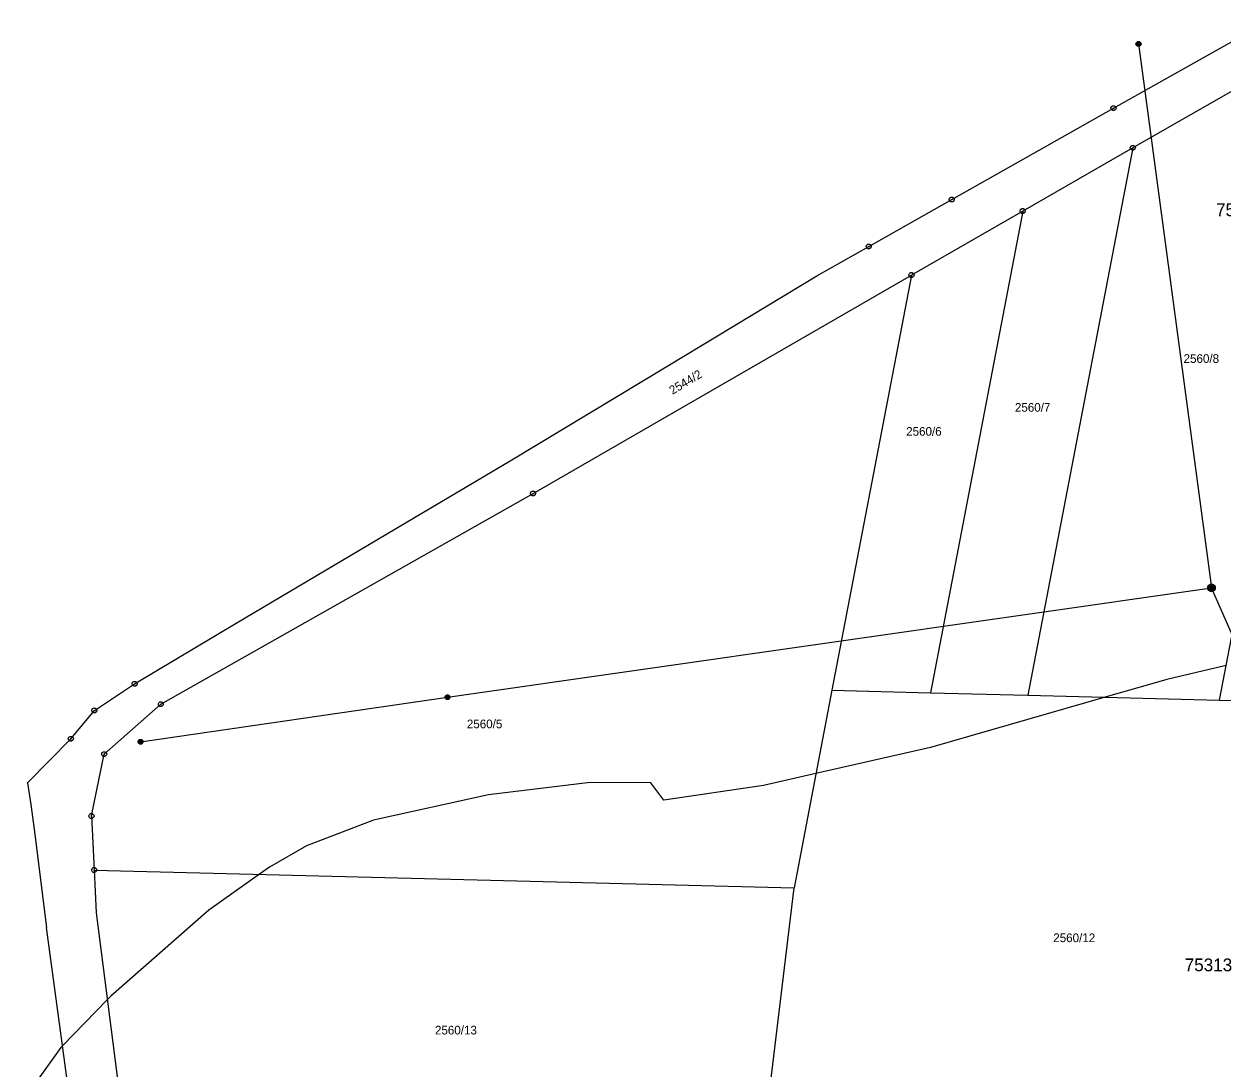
# Model space of a CAD drawing. Extents: x -760611 to -758411, y -1176479 to -1174807.
# Drawn here: x -759710.8 to -759476.2, y -1175348.2 to -1175143.7 of the extents above; entities that cross this region are included whole.
import ezdxf

# ---------------------------------------------------------------- set-up
doc = ezdxf.new("R2010")
doc.units = 0
for name, color, linetype in [('1', 7, 'Continuous'), ('11', 7, 'Continuous'), ('2', 7, 'Continuous'), ('6', 7, 'Continuous'), ('8', 7, 'Continuous')]:
    doc.layers.add(name, color=color, linetype=linetype)

msp = doc.modelspace()

# ---------------------------------------------------------------- linework, layer by layer
at = {"layer": '1'}
for p, q in [((-759497.47, -1175160.23), (-759471.7, -1175145.7)), ((-759451.36, -1175143.73), (-759493.7, -1175167.99)), ((-759476.73, -1175276.15), (-759451.36, -1175143.73)), ((-759529.17, -1175178.14), (-759497.47, -1175160.23)), ((-759493.7, -1175167.99), (-759515.25, -1175180.38)), ((-759493.7, -1175167.99), (-759514.23, -1175275.19)), ((-759545.4, -1175187.31), (-759529.17, -1175178.14)), ((-759515.25, -1175180.38), (-759537.04, -1175192.91)), ((-759515.25, -1175180.38), (-759533.32, -1175274.71)), ((-759555.57, -1175193.05), (-759545.4, -1175187.31)), ((-759611.14, -1175235.69), (-759537.04, -1175192.91)), ((-759584.77, -1175210.68), (-759555.57, -1175193.05)), ((-759537.04, -1175192.91), (-759552.61, -1175274.21)), ((-759615.59, -1175229.29), (-759584.77, -1175210.68)), ((-759669.25, -1175261.1), (-759615.59, -1175229.29)), ((-759684.03, -1175276.97), (-759611.14, -1175235.69)), ((-759689.15, -1175272.97), (-759669.25, -1175261.1)), ((-759697.03, -1175278.2), (-759689.15, -1175272.97)), ((-759552.61, -1175274.21), (-759560.03, -1175312.95)), ((-759552.61, -1175274.21), (-759533.32, -1175274.71)), ((-759533.32, -1175274.71), (-759514.23, -1175275.19)), ((-759695.11, -1175286.75), (-759684.03, -1175276.97)), ((-759514.23, -1175275.19), (-759476.73, -1175276.15)), ((-759476.73, -1175276.15), (-759458.35, -1175276.62)), ((-759701.63, -1175283.75), (-759697.03, -1175278.2)), ((-759701.63, -1175283.75), (-759710.1, -1175292.36)), ((-759697.6, -1175298.86), (-759695.11, -1175286.75)), ((-759710.1, -1175292.36), (-759709.49, -1175296.58)), ((-759709.49, -1175296.58), (-759708.79, -1175301.41)), ((-759697.6, -1175298.86), (-759697.08, -1175309.45)), ((-759708.79, -1175301.41), (-759706.43, -1175320.68)), ((-759697.08, -1175309.45), (-759696.67, -1175317.85)), ((-759697.08, -1175309.45), (-759560.03, -1175312.95)), ((-759565.54, -1175358.51), (-759560.03, -1175312.95)), ((-759696.67, -1175317.85), (-759689.49, -1175374.27)), ((-759691.89, -1175426.78), (-759706.43, -1175320.68))]:
    msp.add_line(p, q, dxfattribs=at)
at = {"layer": '11'}
msp.add_lwpolyline([(-759475.44, -1175269.41), (-759487.07, -1175272.11), (-759499.12, -1175275.58), (-759533.34, -1175285.42), (-759555.74, -1175290.53), (-759566.01, -1175292.87), (-759585.53, -1175295.74), (-759588.06, -1175292.34), (-759599.93, -1175292.28), (-759619.87, -1175294.72), (-759642.36, -1175299.69), (-759655.52, -1175304.7), (-759662.75, -1175308.89), (-759664.71, -1175310.28), (-759674.65, -1175317.3), (-759693.79, -1175334.13), (-759694.5, -1175334.86), (-759703.25, -1175343.89), (-759703.58, -1175344.23), (-759710.82, -1175354.35)], dxfattribs=at)
at = {"layer": '6'}
for p, q in [((-759492.59, -1175147.64), (-759478.28, -1175254.17)), ((-759627.89, -1175275.6), (-759478.28, -1175254.17)), ((-759403.75, -1175424.27), (-759478.28, -1175254.17)), ((-759687.99, -1175284.33), (-759627.89, -1175275.6))]:
    msp.add_line(p, q, dxfattribs=at)
for points in [[(-759492.74, -1175147.16), (-759492.43, -1175147.16), (-759492.18, -1175147.34), (-759492.08, -1175147.63), (-759492.18, -1175147.92), (-759492.43, -1175148.1), (-759492.74, -1175148.1), (-759492.99, -1175147.92), (-759493.09, -1175147.63), (-759492.99, -1175147.34), (-759492.74, -1175147.16), (-759492.71, -1175147.2), (-759492.47, -1175147.2), (-759492.31, -1175147.28), (-759492.87, -1175147.28), (-759492.95, -1175147.36), (-759492.23, -1175147.36), (-759492.23, -1175147.44), (-759492.95, -1175147.44), (-759492.99, -1175147.52), (-759492.19, -1175147.52), (-759492.15, -1175147.6), (-759493.03, -1175147.6), (-759493.03, -1175147.68), (-759492.15, -1175147.68), (-759492.18, -1175147.76), (-759492.99, -1175147.76), (-759492.98, -1175147.84), (-759492.17, -1175147.84), (-759492.22, -1175147.92), (-759492.94, -1175147.92), (-759492.86, -1175148), (-759492.3, -1175148), (-759492.41, -1175148.08), (-759492.75, -1175148.08)], [(-759478.78, -1175253.67), (-759477.78, -1175253.67), (-759477.78, -1175254.67), (-759478.78, -1175254.67), (-759478.78, -1175253.67), (-759478.72, -1175253.73), (-759477.84, -1175253.73), (-759477.84, -1175253.81), (-759478.72, -1175253.81), (-759478.72, -1175253.89), (-759477.84, -1175253.89), (-759477.84, -1175253.97), (-759478.72, -1175253.97), (-759478.72, -1175254.05), (-759477.84, -1175254.05), (-759477.84, -1175254.13), (-759478.72, -1175254.13), (-759478.72, -1175254.21), (-759477.84, -1175254.21), (-759477.84, -1175254.29), (-759478.72, -1175254.29), (-759478.72, -1175254.37), (-759477.84, -1175254.37), (-759477.84, -1175254.45), (-759478.72, -1175254.45), (-759478.72, -1175254.53), (-759477.84, -1175254.53), (-759477.84, -1175254.61), (-759478.72, -1175254.61)], [(-759628.04, -1175275.12), (-759627.73, -1175275.12), (-759627.48, -1175275.3), (-759627.38, -1175275.59), (-759627.48, -1175275.88), (-759627.73, -1175276.06), (-759628.04, -1175276.06), (-759628.29, -1175275.88), (-759628.39, -1175275.59), (-759628.29, -1175275.3), (-759628.04, -1175275.12), (-759628.01, -1175275.16), (-759627.77, -1175275.16), (-759627.61, -1175275.24), (-759628.17, -1175275.24), (-759628.25, -1175275.32), (-759627.53, -1175275.32), (-759627.53, -1175275.4), (-759628.25, -1175275.4), (-759628.29, -1175275.48), (-759627.49, -1175275.48), (-759627.45, -1175275.56), (-759628.33, -1175275.56), (-759628.33, -1175275.64), (-759627.45, -1175275.64), (-759627.48, -1175275.72), (-759628.29, -1175275.72), (-759628.28, -1175275.8), (-759627.47, -1175275.8), (-759627.52, -1175275.88), (-759628.24, -1175275.88), (-759628.16, -1175275.96), (-759627.6, -1175275.96), (-759627.71, -1175276.04), (-759628.05, -1175276.04)], [(-759688.14, -1175283.85), (-759687.83, -1175283.85), (-759687.58, -1175284.03), (-759687.48, -1175284.32), (-759687.58, -1175284.61), (-759687.83, -1175284.79), (-759688.14, -1175284.79), (-759688.39, -1175284.61), (-759688.49, -1175284.32), (-759688.39, -1175284.03), (-759688.14, -1175283.85), (-759688.11, -1175283.89), (-759687.87, -1175283.89), (-759687.71, -1175283.97), (-759688.27, -1175283.97), (-759688.35, -1175284.05), (-759687.63, -1175284.05), (-759687.63, -1175284.13), (-759688.35, -1175284.13), (-759688.39, -1175284.21), (-759687.59, -1175284.21), (-759687.55, -1175284.29), (-759688.43, -1175284.29), (-759688.43, -1175284.37), (-759687.55, -1175284.37), (-759687.58, -1175284.45), (-759688.39, -1175284.45), (-759688.38, -1175284.53), (-759687.57, -1175284.53), (-759687.62, -1175284.61), (-759688.34, -1175284.61), (-759688.26, -1175284.69), (-759687.7, -1175284.69), (-759687.81, -1175284.77), (-759688.15, -1175284.77)]]:
    msp.add_lwpolyline(points, dxfattribs=at)
at = {"layer": '8'}
for p, q in [((-759497.59, -1175160.23), (-759497.35, -1175160.23)), ((-759493.82, -1175167.99), (-759493.58, -1175167.99)), ((-759529.29, -1175178.14), (-759529.05, -1175178.14)), ((-759515.37, -1175180.38), (-759515.13, -1175180.38)), ((-759545.52, -1175187.31), (-759545.28, -1175187.31)), ((-759537.16, -1175192.91), (-759536.92, -1175192.91)), ((-759611.26, -1175235.69), (-759611.02, -1175235.69)), ((-759478.33, -1175254.17), (-759478.23, -1175254.17)), ((-759689.27, -1175272.97), (-759689.03, -1175272.97)), ((-759684.15, -1175276.97), (-759683.91, -1175276.97)), ((-759697.15, -1175278.2), (-759696.91, -1175278.2)), ((-759701.75, -1175283.75), (-759701.51, -1175283.75)), ((-759695.23, -1175286.75), (-759694.99, -1175286.75)), ((-759697.72, -1175298.86), (-759697.48, -1175298.86)), ((-759697.2, -1175309.45), (-759696.96, -1175309.45))]:
    msp.add_line(p, q, dxfattribs=at)
for points in [[(-759497.32, -1175159.75), (-759497.07, -1175159.93), (-759496.97, -1175160.22), (-759497.07, -1175160.51), (-759497.32, -1175160.69), (-759497.63, -1175160.69), (-759497.88, -1175160.51), (-759497.98, -1175160.22), (-759497.88, -1175159.93), (-759497.63, -1175159.75)], [(-759493.55, -1175167.51), (-759493.3, -1175167.69), (-759493.2, -1175167.98), (-759493.3, -1175168.27), (-759493.55, -1175168.45), (-759493.86, -1175168.45), (-759494.11, -1175168.27), (-759494.21, -1175167.98), (-759494.11, -1175167.69), (-759493.86, -1175167.51)], [(-759529.02, -1175177.66), (-759528.77, -1175177.84), (-759528.67, -1175178.13), (-759528.77, -1175178.42), (-759529.02, -1175178.6), (-759529.33, -1175178.6), (-759529.58, -1175178.42), (-759529.68, -1175178.13), (-759529.58, -1175177.84), (-759529.33, -1175177.66)], [(-759515.1, -1175179.9), (-759514.85, -1175180.08), (-759514.75, -1175180.37), (-759514.85, -1175180.66), (-759515.1, -1175180.84), (-759515.41, -1175180.84), (-759515.66, -1175180.66), (-759515.76, -1175180.37), (-759515.66, -1175180.08), (-759515.41, -1175179.9)], [(-759545.25, -1175186.83), (-759545, -1175187.01), (-759544.9, -1175187.3), (-759545, -1175187.59), (-759545.25, -1175187.77), (-759545.56, -1175187.77), (-759545.81, -1175187.59), (-759545.91, -1175187.3), (-759545.81, -1175187.01), (-759545.56, -1175186.83)], [(-759536.89, -1175192.43), (-759536.64, -1175192.61), (-759536.54, -1175192.9), (-759536.64, -1175193.19), (-759536.89, -1175193.37), (-759537.2, -1175193.37), (-759537.45, -1175193.19), (-759537.55, -1175192.9), (-759537.45, -1175192.61), (-759537.2, -1175192.43)], [(-759610.99, -1175235.21), (-759610.74, -1175235.39), (-759610.64, -1175235.68), (-759610.74, -1175235.97), (-759610.99, -1175236.15), (-759611.3, -1175236.15), (-759611.55, -1175235.97), (-759611.65, -1175235.68), (-759611.55, -1175235.39), (-759611.3, -1175235.21)], [(-759478.09, -1175253.45), (-759477.75, -1175253.64), (-759477.56, -1175253.98), (-759477.56, -1175254.37), (-759477.75, -1175254.71), (-759478.09, -1175254.9), (-759478.48, -1175254.9), (-759478.82, -1175254.71), (-759479.01, -1175254.37), (-759479.01, -1175253.98), (-759478.82, -1175253.64), (-759478.48, -1175253.45)], [(-759689, -1175272.49), (-759688.75, -1175272.67), (-759688.65, -1175272.96), (-759688.75, -1175273.25), (-759689, -1175273.43), (-759689.31, -1175273.43), (-759689.56, -1175273.25), (-759689.66, -1175272.96), (-759689.56, -1175272.67), (-759689.31, -1175272.49)], [(-759683.88, -1175276.49), (-759683.63, -1175276.67), (-759683.53, -1175276.96), (-759683.63, -1175277.25), (-759683.88, -1175277.43), (-759684.19, -1175277.43), (-759684.44, -1175277.25), (-759684.54, -1175276.96), (-759684.44, -1175276.67), (-759684.19, -1175276.49)], [(-759696.88, -1175277.72), (-759696.63, -1175277.9), (-759696.53, -1175278.19), (-759696.63, -1175278.48), (-759696.88, -1175278.66), (-759697.19, -1175278.66), (-759697.44, -1175278.48), (-759697.54, -1175278.19), (-759697.44, -1175277.9), (-759697.19, -1175277.72)], [(-759701.48, -1175283.27), (-759701.23, -1175283.45), (-759701.13, -1175283.74), (-759701.23, -1175284.03), (-759701.48, -1175284.21), (-759701.79, -1175284.21), (-759702.04, -1175284.03), (-759702.14, -1175283.74), (-759702.04, -1175283.45), (-759701.79, -1175283.27)], [(-759694.96, -1175286.27), (-759694.71, -1175286.45), (-759694.61, -1175286.74), (-759694.71, -1175287.03), (-759694.96, -1175287.21), (-759695.27, -1175287.21), (-759695.52, -1175287.03), (-759695.62, -1175286.74), (-759695.52, -1175286.45), (-759695.27, -1175286.27)], [(-759697.45, -1175298.38), (-759697.2, -1175298.56), (-759697.1, -1175298.85), (-759697.2, -1175299.14), (-759697.45, -1175299.32), (-759697.76, -1175299.32), (-759698.01, -1175299.14), (-759698.11, -1175298.85), (-759698.01, -1175298.56), (-759697.76, -1175298.38)], [(-759696.93, -1175308.97), (-759696.68, -1175309.15), (-759696.58, -1175309.44), (-759696.68, -1175309.73), (-759696.93, -1175309.91), (-759697.24, -1175309.91), (-759697.49, -1175309.73), (-759697.59, -1175309.44), (-759697.49, -1175309.15), (-759697.24, -1175308.97)]]:
    msp.add_lwpolyline(points, close=True, dxfattribs=at)

# ---------------------------------------------------------------- texts
at = {"layer": '11'}
for s, p in [('75303', (-759477.41, -1175181.38)), ('75313', (-759483.54, -1175329.27))]:
    msp.add_text(s, height=2.5, dxfattribs=at).set_placement(p)
at = {"layer": '2'}
for s, p in [('2560/8', (-759483.76, -1175210.12)), ('2560/7', (-759516.79, -1175219.68)), ('2560/6', (-759538.08, -1175224.38)), ('2560/5', (-759624.1, -1175281.68)), ('2560/12', (-759509.28, -1175323.57)), ('2560/13', (-759630.35, -1175341.65))]:
    msp.add_text(s, height=1.7, dxfattribs=at).set_placement(p)
msp.add_text('2544/2', height=1.7, rotation=30.7105, dxfattribs=at).set_placement((-759583.84, -1175216.38))

doc.saveas('drawing.dxf')
